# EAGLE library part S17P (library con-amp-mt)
AMP MT CONNECTOR
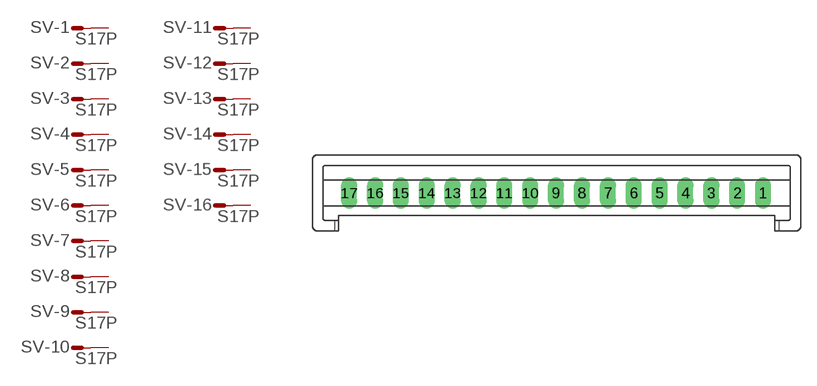
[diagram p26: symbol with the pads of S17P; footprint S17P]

Designator prefix SV; gates -1=M -2=M -3=M -4=M -5=M -6=M -7=M -8=M -9=M -10=M -11=M -12=M -13=M -14=M -15=M -16=M -17=M

## S17P (OC_FARNELL: unknown; OC_NEWARK: unknown)  [S17P]
1  -1:S  pas
2  -2:S  pas
3  -3:S  pas
4  -4:S  pas
5  -5:S  pas
6  -6:S  pas
7  -7:S  pas
8  -8:S  pas
9  -9:S  pas
10  -10:S  pas
11  -11:S  pas
12  -12:S  pas
13  -13:S  pas
14  -14:S  pas
15  -15:S  pas
16  -16:S  pas
17  -17:S  pas

## Footprint S17P (pad centres in mm)
AMP MT CONNECTOR
drill 1.016 long: 1 20,0; 2 17.5,0; 3 15,0; 4 12.5,0; 5 10,0; 6 7.5,0; 7 5,0; 8 2.5,0; 9 0,0; 10 -2.5,0; 11 -5,0; 12 -7.5,0; 13 -10,0; 14 -12.5,0; 15 -15,0; 16 -17.49,0; 17 -20.005,0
